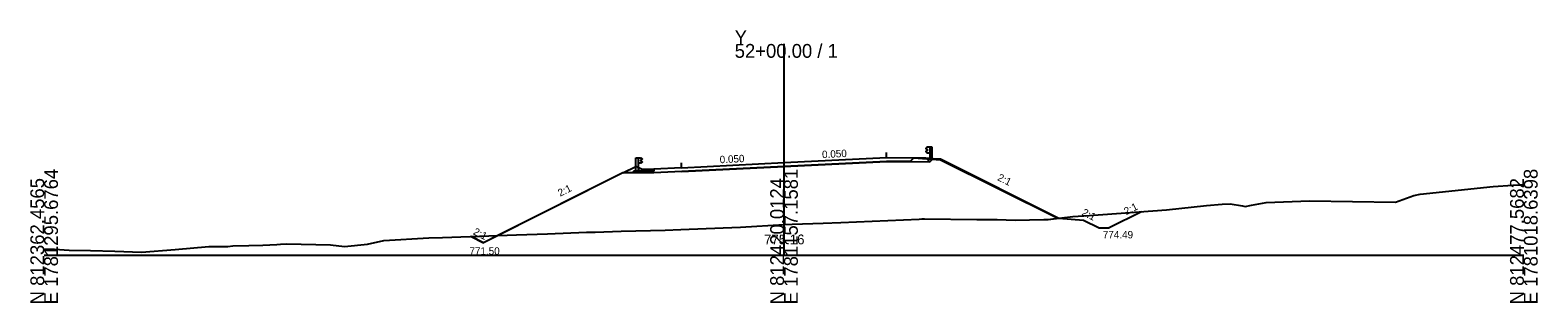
# Model space of a CAD drawing. Extents: x -12583 to 5303, y -44 to 25667.
# Drawn here: x 3997.2 to 4302.8, y 2490.3 to 2545.6 of the extents above; entities that cross this region are included whole.
import ezdxf

# ---------------------------------------------------------------- set-up
doc = ezdxf.new("R2010")
doc.units = 0
for name, color, linetype in [('Exist Cross Section Cell', 7, 'Continuous'), ('Exist XS Center Line Elevation Label', 7, 'Continuous'), ('Exist XS Ground Line', 7, 'Continuous'), ('Prop XS DDE', 7, 'Continuous'), ('Prop XS Ditch Standard Text', 7, 'Continuous'), ('Prop XS Dump Level', 7, 'Continuous'), ('Prop XS Earthwork Shape', 7, 'Continuous'), ('Prop XS EOT Tick Mark', 7, 'Continuous'), ('Prop XS Finish Grade', 7, 'Continuous'), ('Prop XS Finish Grade CurbGutter', 7, 'Continuous'), ('Prop XS Finish Grade Earthwork', 7, 'Continuous'), ('Prop XS Finish Grade Paved Shoulder', 7, 'Continuous'), ('Prop XS Finish Grade Pavement', 7, 'Continuous'), ('Prop XS Guardrail', 7, 'Continuous'), ('Prop XS Pvmt Edge Slope', 7, 'Continuous'), ('Prop XS SE Text', 7, 'Continuous'), ('Prop XS Side Slope Text', 7, 'Continuous'), ('Prop XS Subgrade CurbGutter', 7, 'Continuous'), ('Prop XS Subgrade Earthwork', 7, 'Continuous')]:
    doc.layers.add(name, color=color, linetype=linetype)

msp = doc.modelspace()

# ---------------------------------------------------------------- linework, layer by layer
at = {"layer": 'Exist Cross Section Cell'}
for p, q in [((4150, 2500), (4150, 2542.78)), ((4000, 2500), (4150, 2500)), ((4150, 2500), (4300, 2500))]:
    msp.add_line(p, q, dxfattribs=at)
at = {"layer": 'Exist XS Ground Line'}
for p, q in [((4278.99, 2512.35), (4293.75, 2513.87)), ((4293.75, 2513.87), (4297.74, 2514.19)), ((4297.74, 2514.19), (4299.24, 2514.23)), ((4299.24, 2514.23), (4300, 2514.26)), ((4227.55, 2509.19), (4235.63, 2510.06)), ((4235.63, 2510.06), (4238.87, 2510.28)), ((4238.87, 2510.28), (4240.49, 2510.38)), ((4240.49, 2510.38), (4242.93, 2509.98)), ((4242.93, 2509.98), (4243.49, 2509.86)), ((4243.49, 2509.86), (4244.76, 2510.13)), ((4244.76, 2510.13), (4247.73, 2510.68)), ((4247.73, 2510.68), (4256.57, 2510.97)), ((4256.57, 2510.97), (4273.95, 2510.73)), ((4273.95, 2510.73), (4277.69, 2512.04)), ((4277.69, 2512.04), (4278.99, 2512.35)), ((4157.91, 2506.46), (4161.51, 2506.61)), ((4161.51, 2506.61), (4177.41, 2507.29)), ((4177.41, 2507.29), (4177.94, 2507.31)), ((4177.94, 2507.31), (4178.47, 2507.31)), ((4178.47, 2507.31), (4189.12, 2507.23)), ((4189.12, 2507.23), (4193.19, 2507.18)), ((4193.19, 2507.18), (4196.9, 2507.1)), ((4196.9, 2507.1), (4202.66, 2507.18)), ((4202.66, 2507.18), (4203.55, 2507.23)), ((4203.55, 2507.23), (4208.58, 2507.83)), ((4208.58, 2507.83), (4211.89, 2508.01)), ((4211.89, 2508.01), (4227.55, 2509.19)), ((4078.01, 2503.48), (4080.73, 2503.54)), ((4080.73, 2503.54), (4093.87, 2504.03)), ((4093.87, 2504.03), (4095.77, 2504.09)), ((4095.77, 2504.09), (4102.03, 2504.31)), ((4102.03, 2504.31), (4109.99, 2504.63)), ((4109.99, 2504.63), (4111.7, 2504.62)), ((4111.7, 2504.62), (4116.99, 2504.81)), ((4116.99, 2504.81), (4125.9, 2505.02)), ((4125.9, 2505.02), (4129.09, 2505.19)), ((4129.09, 2505.19), (4137.64, 2505.52)), ((4137.64, 2505.52), (4141.21, 2505.67)), ((4141.21, 2505.67), (4150, 2506.16)), ((4150, 2506.16), (4151.63, 2506.26)), ((4151.63, 2506.26), (4157.91, 2506.46)), ((4000, 2501.21), (4002.09, 2501.17)), ((4002.09, 2501.17), (4005.1, 2500.96)), ((4005.1, 2500.96), (4009.39, 2500.94)), ((4009.39, 2500.94), (4014.33, 2500.77)), ((4014.33, 2500.77), (4019.72, 2500.58)), ((4019.72, 2500.58), (4026.57, 2501.12)), ((4026.57, 2501.12), (4033.41, 2501.74)), ((4033.41, 2501.74), (4037.25, 2501.7)), ((4037.25, 2501.7), (4038.24, 2501.84)), ((4038.24, 2501.84), (4041.48, 2501.91)), ((4041.48, 2501.91), (4044.32, 2501.98)), ((4044.32, 2501.98), (4047.16, 2502.15)), ((4047.16, 2502.15), (4047.89, 2502.2)), ((4047.89, 2502.2), (4049.1, 2502.26)), ((4049.1, 2502.26), (4058.08, 2502.05)), ((4058.08, 2502.05), (4060.88, 2501.7)), ((4060.88, 2501.7), (4065.55, 2502.21)), ((4065.55, 2502.21), (4068.89, 2502.94)), ((4068.89, 2502.94), (4078.01, 2503.48))]:
    msp.add_line(p, q, dxfattribs=at)
at = {"layer": 'Prop XS DDE'}
for p, q in [((4205.74, 2507.5), (4210.74, 2507.08)), ((4210.74, 2507.08), (4213.91, 2505.49)), ((4222.47, 2508.77), (4215.91, 2505.49)), ((4213.91, 2505.49), (4215.91, 2505.49))]:
    msp.add_line(p, q, dxfattribs=at)
at = {"layer": 'Prop XS Dump Level'}
for p, q in [((4150, 2518.74), (4170.75, 2519.78)), ((4129.25, 2517.7), (4150, 2518.74))]:
    msp.add_line(p, q, dxfattribs=at)
at = {"layer": 'Prop XS Earthwork Shape'}
for points in [[(4178.47, 2507.31), (4189.12, 2507.23), (4193.19, 2507.18), (4196.9, 2507.1), (4202.66, 2507.18), (4203.55, 2507.23), (4205.35, 2507.45), (4181.75, 2519.25), (4176.24, 2519.63), (4175.55, 2518.94), (4170.77, 2518.99), (4150.04, 2517.95), (4129.29, 2516.91), (4123.58, 2516.63), (4119.19, 2516.63), (4117.32, 2516.63), (4091.99, 2503.96), (4093.87, 2504.03), (4095.77, 2504.09), (4102.03, 2504.31), (4109.99, 2504.63), (4111.7, 2504.62), (4116.99, 2504.81), (4125.9, 2505.02), (4129.09, 2505.19), (4137.64, 2505.52), (4141.21, 2505.67), (4150, 2506.16), (4151.63, 2506.26), (4157.91, 2506.46), (4161.51, 2506.61), (4177.41, 2507.29), (4177.94, 2507.31)], [(4086.55, 2503.76), (4091.99, 2503.96), (4089.07, 2502.5)]]:
    msp.add_lwpolyline(points, close=True, dxfattribs=at)
at = {"layer": 'Prop XS EOT Tick Mark'}
for p, q in [((4170.75, 2519.78), (4170.75, 2520.78)), ((4129.25, 2517.7), (4129.25, 2518.7))]:
    msp.add_line(p, q, dxfattribs=at)
at = {"layer": 'Prop XS Finish Grade'}
for p, q in [((4178.75, 2519.7), (4180.24, 2519.59)), ((4117.32, 2516.63), (4119.98, 2517.96)), ((4120.56, 2517.67), (4119.98, 2517.96))]:
    msp.add_line(p, q, dxfattribs=at)
at = {"layer": 'Prop XS Finish Grade CurbGutter'}
for p, q in [((4121.25, 2517.33), (4120.56, 2517.67)), ((4123.58, 2517.42), (4121.25, 2517.33))]:
    msp.add_line(p, q, dxfattribs=at)
at = {"layer": 'Prop XS Finish Grade Earthwork'}
for p, q in [((4180.24, 2519.59), (4181.75, 2519.49)), ((4181.75, 2519.49), (4205.74, 2507.5)), ((4117.32, 2516.63), (4089.07, 2502.5)), ((4086.55, 2503.76), (4089.07, 2502.5))]:
    msp.add_line(p, q, dxfattribs=at)
at = {"layer": 'Prop XS Finish Grade Paved Shoulder'}
for p, q in [((4170.75, 2519.78), (4178.75, 2519.7)), ((4129.25, 2517.7), (4123.58, 2517.42))]:
    msp.add_line(p, q, dxfattribs=at)
at = {"layer": 'Prop XS Finish Grade Pavement'}
for p, q in [((4150, 2518.74), (4170.75, 2519.78)), ((4129.25, 2517.7), (4150, 2518.74))]:
    msp.add_line(p, q, dxfattribs=at)
at = {"layer": 'Prop XS Guardrail'}
for p, q in [((4119.93, 2519.72), (4120.43, 2519.72)), ((4119.93, 2517.22), (4119.93, 2519.72)), ((4120.43, 2519.72), (4120.93, 2519.72)), ((4120.43, 2519.72), (4120.43, 2517.22)), ((4120.93, 2519.72), (4121.22, 2519.52)), ((4121.22, 2519.4), (4120.93, 2519.2)), ((4120.93, 2519.2), (4120.93, 2519.11)), ((4120.93, 2519.11), (4121.22, 2518.91)), ((4121.22, 2519.52), (4121.25, 2519.46)), ((4121.25, 2519.46), (4121.22, 2519.4)), ((4121.22, 2518.91), (4121.25, 2518.85)), ((4121.25, 2518.85), (4121.22, 2518.79)), ((4178.78, 2521.67), (4178.75, 2521.61)), ((4178.75, 2521.61), (4178.78, 2521.55)), ((4178.78, 2521.05), (4178.75, 2520.99)), ((4178.75, 2520.99), (4178.78, 2520.93)), ((4179.07, 2521.87), (4178.78, 2521.67)), ((4178.78, 2521.55), (4179.07, 2521.35)), ((4179.07, 2521.25), (4178.78, 2521.05)), ((4178.78, 2520.93), (4179.07, 2520.73)), ((4179.57, 2521.87), (4179.07, 2521.87)), ((4179.07, 2521.35), (4179.07, 2521.25)), ((4179.07, 2520.73), (4179.57, 2520.73)), ((4180.07, 2521.87), (4179.57, 2521.87)), ((4179.57, 2521.87), (4179.57, 2519.37)), ((4180.07, 2519.37), (4180.07, 2521.87)), ((4120.93, 2518.59), (4120.43, 2518.59)), ((4121.22, 2518.79), (4120.93, 2518.59))]:
    msp.add_line(p, q, dxfattribs=at)
at = {"layer": 'Prop XS Pvmt Edge Slope'}
for p, q in [((4178.75, 2519.7), (4179.55, 2518.9)), ((4119.56, 2517), (4119.19, 2516.63)), ((4120.56, 2517), (4119.56, 2517))]:
    msp.add_line(p, q, dxfattribs=at)
at = {"layer": 'Prop XS Subgrade CurbGutter'}
for p, q in [((4120.56, 2517), (4120.56, 2517.67)), ((4123.58, 2517), (4120.56, 2517)), ((4123.58, 2517.42), (4123.58, 2517))]:
    msp.add_line(p, q, dxfattribs=at)
at = {"layer": 'Prop XS Subgrade Earthwork'}
for p, q in [((4150.04, 2517.95), (4170.77, 2518.99)), ((4170.77, 2518.99), (4179.55, 2518.9)), ((4179.55, 2518.9), (4180.24, 2519.59)), ((4119.19, 2516.63), (4117.32, 2516.63)), ((4123.58, 2516.63), (4119.19, 2516.63)), ((4129.29, 2516.91), (4123.58, 2516.63)), ((4129.29, 2516.91), (4150.04, 2517.95))]:
    msp.add_line(p, q, dxfattribs=at)

# ---------------------------------------------------------------- texts
at = {"layer": 'Exist Cross Section Cell'}
for s, p in [('Y', (4140, 2542.78)), ('52+00.00 / 1', (4140, 2539.98))]:
    msp.add_text(s, height=2.8, dxfattribs=at).set_placement(p)
for s, p in [('E 1781295.6764', (4002.8, 2490)), ('E 1781157.1581', (4152.8, 2490)), ('E 1781018.6398', (4302.8, 2490)), ('N 812362.4565', (4000, 2490)), ('N 812420.0124', (4150, 2490)), ('N 812477.5682', (4300, 2490))]:
    msp.add_text(s, height=2.8, rotation=90, dxfattribs=at).set_placement(p)
at = {"layer": 'Exist XS Center Line Elevation Label'}
msp.add_text('775.16', height=2, dxfattribs=at).set_placement((4145.97, 2502.16))
at = {"layer": 'Prop XS Ditch Standard Text'}
for s, p in [('774.49', (4214.64, 2503.38)), ('771.50', (4086.22, 2500.06))]:
    msp.add_text(s, height=1.5, dxfattribs=at).set_placement(p)
at = {"layer": 'Prop XS Dump Level'}
for p in [(4178.75, 2519.42), (4123.58, 2517.38)]:
    msp.add_text('Case2', height=0.04, dxfattribs=at).set_placement(p)
at = {"layer": 'Prop XS SE Text'}
for p in [(4137, 2518.59), (4157.75, 2519.63)]:
    msp.add_text('0.050', height=1.5, rotation=2.8624, dxfattribs=at).set_placement(p)
at = {"layer": 'Prop XS Side Slope Text'}
for rotation, p in [(333.4349, (4193.14, 2515.23)), (26.5651, (4104.61, 2511.8)), (26.5651, (4219.39, 2508.07)), (333.4349, (4210.25, 2508.16)), (333.4349, (4086.84, 2504.26))]:
    msp.add_text('2:1', height=1.5, rotation=rotation, dxfattribs=at).set_placement(p)

doc.saveas('drawing.dxf')
